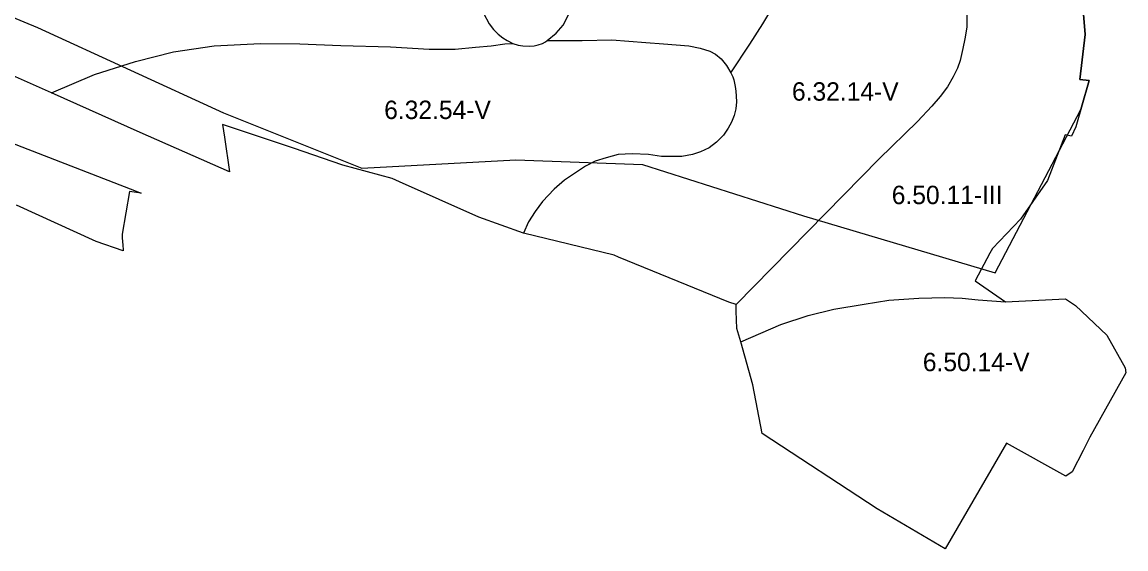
# Model space of a CAD drawing. Extents: x -555156 to -540209, y -1046851 to -1035695.
# Drawn here: x -543756 to -543156, y -1042725 to -1042439 of the extents above; entities that cross this region are included whole.
import ezdxf

# ---------------------------------------------------------------- set-up
doc = ezdxf.new("R2010")
doc.units = 0
for name, color, linetype in [('Vrstva 27', 7, 'Continuous'), ('Vrstva 28', 7, 'Continuous'), ('Vrstva 29', 7, 'Continuous')]:
    doc.layers.add(name, color=color, linetype=linetype)

msp = doc.modelspace()

# ---------------------------------------------------------------- linework, layer by layer
at = {"layer": 'Vrstva 28'}
for points in [[(-543244.59, -1042217.88), (-543247.14, -1042222.41), (-543224.11, -1042247.37), (-543214.05, -1042282.33), (-543205.04, -1042336.81), (-543205.6, -1042366.71), (-543185.21, -1042418.55), (-543178.94, -1042434.51), (-543177.97, -1042445.51), (-543180.87, -1042470.03), (-543175.77, -1042470.5), (-543183.08, -1042495.73), (-543185.4, -1042500.78), (-543188.89, -1042500.08), (-543198.36, -1042525.01), (-543213.09, -1042545.98), (-543228.37, -1042561.85), (-543229.71, -1042564.4), (-543237.68, -1042579.56), (-543221.29, -1042590.89)], [(-543470.32, -1042448.88), (-543465.5, -1042444.9), (-543461.62, -1042440.42), (-543458.59, -1042434.48), (-543455.81, -1042426.97), (-543452.66, -1042417.15), (-543448.66, -1042402.37), (-543440.79, -1042378.14), (-543431.47, -1042353.05)], [(-543370.54, -1042466.34), (-543360.25, -1042450.83), (-543353.1, -1042439.81), (-543345.49, -1042427), (-543341.01, -1042415.73), (-543337.38, -1042402.77), (-543332.29, -1042383.98), (-543330.23, -1042373.8), (-543327.47, -1042350.59)], [(-543294.11, -1042350.17), (-543283.46, -1042358.04), (-543274.13, -1042366.28), (-543265.41, -1042374.16), (-543258.87, -1042381.31), (-543253.91, -1042388.7), (-543250.42, -1042397.03), (-543247.03, -1042408.54), (-543244.37, -1042419.08), (-543242.92, -1042427.08), (-543242.19, -1042434.59), (-543242.31, -1042441.62), (-543243.28, -1042447.92), (-543244.37, -1042453.25), (-543245.82, -1042459.67), (-543247.4, -1042463.79), (-543249.7, -1042468.64), (-543252.85, -1042474.09), (-543256.72, -1042479.3), (-543261.32, -1042484.51), (-543269.07, -1042492.79), (-543289.89, -1042513.14), (-543367.72, -1042592.26)], [(-543505.02, -1042433.99), (-543501.83, -1042439.72), (-543499.62, -1042442.89), (-543497.05, -1042445.46), (-543494.48, -1042447.44), (-543492.18, -1042448.86), (-543489.01, -1042450.46)], [(-543739.84, -1042477.33), (-543716.42, -1042467.37), (-543694.17, -1042460.16), (-543673.4, -1042455.07), (-543651.36, -1042451.67), (-543626.13, -1042450.4), (-543604.73, -1042450.61), (-543582.48, -1042451.46), (-543555.56, -1042452.31), (-543534.58, -1042453.58), (-543520.38, -1042453.58), (-543509.36, -1042452.52), (-543500.76, -1042451.67), (-543493.37, -1042450.71), (-543489.01, -1042450.46)], [(-543489.01, -1042450.46), (-543486.21, -1042451.36), (-543483.52, -1042451.71), (-543480.2, -1042451.87), (-543477.39, -1042451.63), (-543475.3, -1042451.12), (-543472.93, -1042450.37), (-543471.34, -1042449.5), (-543470.32, -1042448.88)], [(-543470.32, -1042448.88), (-543451.31, -1042448.76), (-543435.2, -1042448.52), (-543416.67, -1042449.97)], [(-543416.67, -1042449.97), (-543407.13, -1042450.62), (-543400.28, -1042451.18), (-543393.29, -1042451.73), (-543387.13, -1042452.91), (-543382.01, -1042454.64), (-543378.9, -1042456.16), (-543375.85, -1042458.73), (-543372.96, -1042462.34), (-543370.54, -1042466.34)], [(-543739.84, -1042477.33), (-543770.99, -1042463.46), (-543782.33, -1042458.41), (-543792.12, -1042454.05)], [(-543370.54, -1042466.34), (-543369.91, -1042467.4), (-543369.42, -1042468.64), (-543368.92, -1042470.25), (-543368.51, -1042472.08), (-543368.15, -1042473.74), (-543367.83, -1042476.4), (-543367.62, -1042479.05), (-543367.41, -1042482.23), (-543367.9, -1042485.97), (-543368.66, -1042489.64), (-543370.11, -1042493.17), (-543372.05, -1042496.5), (-543374.51, -1042500.2), (-543378.38, -1042504.08), (-543382.38, -1042507.23), (-543387.1, -1042509.41), (-543391.46, -1042510.86), (-543397.15, -1042511.83), (-543402.97, -1042511.95), (-543408.3, -1042511.83), (-543415.32, -1042510.86), (-543424.16, -1042510.38), (-543431.79, -1042510.86), (-543438.33, -1042512.56), (-543444.26, -1042514.5), (-543449.47, -1042517.16), (-543454.44, -1042520.44), (-543460.86, -1042524.68), (-543466.55, -1042529.64), (-543472.85, -1042536.31), (-543476.96, -1042541.76), (-543480.48, -1042547.34), (-543483.19, -1042553.62)], [(-543483.19, -1042553.62), (-543507.43, -1042544.83), (-543550.66, -1042525.64), (-543554.61, -1042523.89), (-543581.39, -1042516.54), (-543608.28, -1042507.31), (-543616.31, -1042504.56), (-543646.85, -1042494.45), (-543645.83, -1042501.33), (-543643.01, -1042520.26), (-543691.54, -1042498.84), (-543739.84, -1042477.33)], [(-543764.69, -1042503.24), (-543697.04, -1042529.44), (-543691.01, -1042531.78), (-543697.3, -1042530.9), (-543701.4, -1042554.03), (-543701.3, -1042555.64), (-543701.11, -1042558.66), (-543701.06, -1042559.54), (-543700.84, -1042563.16), (-543715.46, -1042558.09), (-543758.78, -1042538.26)], [(-543367.72, -1042592.26), (-543371.66, -1042591.08), (-543431.55, -1042566.59), (-543434.03, -1042565.57), (-543483.19, -1042553.62)], [(-543365.18, -1042612.58), (-543343.39, -1042603.19), (-543328.55, -1042598.31), (-543314.56, -1042594.92), (-543298.03, -1042592.16), (-543284.68, -1042590.04), (-543268.36, -1042588.98), (-543254.16, -1042588.56), (-543244.85, -1042588.86)], [(-543244.85, -1042588.86), (-543236.13, -1042589.89), (-543221.29, -1042590.89)], [(-543365.18, -1042612.58), (-543367.21, -1042605.44), (-543367.57, -1042596.04), (-543367.72, -1042592.26)], [(-543221.29, -1042590.89), (-543188.65, -1042589.23), (-543183.26, -1042592.8), (-543166.24, -1042609.08), (-543156.28, -1042626.85), (-543155.8, -1042629.55), (-543175.33, -1042664.39), (-543179.07, -1042671.76), (-543184.97, -1042683.39), (-543188.51, -1042685.74), (-543220.69, -1042667.71), (-543253.97, -1042725.22), (-543291, -1042703.5), (-543353.51, -1042662.41), (-543358.52, -1042636), (-543365.18, -1042612.58)]]:
    msp.add_lwpolyline(points, dxfattribs=at)
at = {"layer": 'Vrstva 29'}
for points in [[(-543678.559001, -1041899.701006), (-543737.071999, -1041956.557991), (-543796.091003, -1042013.368007), (-543793.823995, -1042080.887994), (-543799.702006, -1042148.137997), (-543806.402996, -1042272.415009), (-543748.249997, -1042283.844996), (-543763.8451, -1042307.420507), (-543779.24, -1042348.49), (-543788.573719, -1042344.469722), (-543832.654991, -1042406.291991), (-543747.419006, -1042441.730009), (-543646.369004, -1042488.114995), (-543571.098993, -1042518.264998), (-543487.431992, -1042513.782999), (-543418.474993, -1042516.304998), (-543330.975997, -1042544.056998), (-543226.944, -1042575.176006), (-543180.376133, -1042486.397776)], [(-543180.376133, -1042486.397776), (-543175.77, -1042470.5), (-543180.87, -1042470.03), (-543177.97, -1042445.51), (-543178.94, -1042434.51), (-543185.21, -1042418.55), (-543205.6, -1042366.71), (-543205.443591, -1042358.358898), (-543243.738993, -1042327.300002), (-543311.772004, -1042282.802003), (-543375.984994, -1042243.767994), (-543388.090995, -1042156.186002), (-543493.434994, -1042095.878002), (-543449.251997, -1041966.777004), (-543375.226998, -1041985.846005), (-543322.264006, -1041941.712996)]]:
    msp.add_lwpolyline(points, dxfattribs=at)

# ---------------------------------------------------------------- texts
at = {"layer": 'Vrstva 27'}
for s, p in [('6.32.14-V', (-543337.310884, -1042481.52)), ('6.32.54-V', (-543558.950884, -1042491.51)), ('6.50.11-III', (-543283.076548, -1042537.78)), ('6.50.14-V', (-543266.180884, -1042628.6))]:
    msp.add_text(s, height=10, dxfattribs=at).set_placement(p)

doc.saveas('drawing.dxf')
